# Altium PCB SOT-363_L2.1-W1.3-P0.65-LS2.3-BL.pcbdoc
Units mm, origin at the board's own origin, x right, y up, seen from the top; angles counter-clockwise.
Board outline 15.06 x 15.43 mm, 2 copper layers (Top Layer, Bottom Layer), stack 0 mm thick; 1 components, 0 nets, 6 pads, 0 vias.
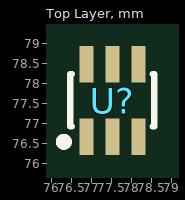
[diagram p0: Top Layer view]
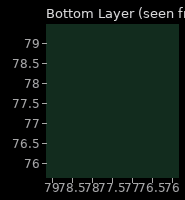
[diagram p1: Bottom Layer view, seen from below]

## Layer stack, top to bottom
Top Layer: signal copper (thickness not stored)
Bottom Layer: signal copper (thickness not stored)

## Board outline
84.91,69.85 69.85,69.85 69.85,85.282 84.91,85.282

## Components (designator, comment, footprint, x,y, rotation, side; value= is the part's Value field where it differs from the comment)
U? "" SOT-363_L2.1-W1.3-P0.65-LS2.3-BL 77.51,77.566 r0 top

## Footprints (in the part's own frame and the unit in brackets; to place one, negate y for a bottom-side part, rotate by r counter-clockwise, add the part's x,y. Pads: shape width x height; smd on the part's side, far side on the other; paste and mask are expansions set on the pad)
SOT-363_L2.1-W1.3-P0.65-LS2.3-BL [mm]
  rect 0.35x0.916 smd: 1(-0.65,-0.908) 2(0,-0.908) 3(0.65,-0.908) 4(0.65,0.908) 5(0,0.908) 6(-0.65,0.908)
  silkscreen extent -1.31,-1.13 1.05,0.66

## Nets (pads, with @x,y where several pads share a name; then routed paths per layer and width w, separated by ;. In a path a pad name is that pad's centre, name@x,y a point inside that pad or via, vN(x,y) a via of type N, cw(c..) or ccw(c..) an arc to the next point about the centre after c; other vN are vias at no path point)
pads on no net: U?.1 U?.2 U?.3 U?.4 U?.5 U?.6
